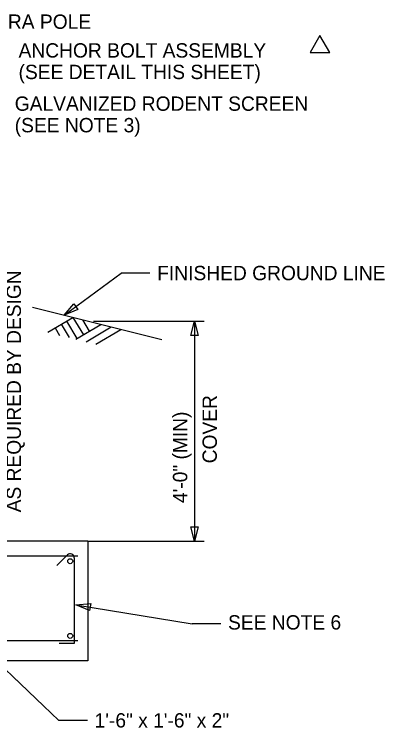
# Model space of a CAD drawing. Extents: x 1299104.6 to 1299141.4, y 239713.3 to 239735.3.
# Drawn here: x 1299113.29 to 1299116.38, y 239717.46 to 239723.43 of the extents above; entities that cross this region are included whole.
import ezdxf

# ---------------------------------------------------------------- set-up
doc = ezdxf.new("R2010")
doc.units = 0
for name, color, linetype in [('DIM TXT', 7, 'Continuous'), ('Level 3', 7, 'Continuous'), ('Level 8', 7, 'Continuous')]:
    doc.layers.add(name, color=color, linetype=linetype)

msp = doc.modelspace()

# ---------------------------------------------------------------- linework, layer by layer
at = {"layer": 'DIM TXT'}
msp.add_lwpolyline([(1299115.759, 239723.1111), (1299115.9214, 239723.1111), (1299115.8402, 239723.2517)], close=True, dxfattribs=at)
at = {"layer": 'Level 3'}
for p, q in [((1299113.4376, 239720.979), (1299114.5182, 239720.7088)), ((1299113.8995, 239719.022), (1299112.3995, 239719.022)), ((1299113.8995, 239719.022), (1299113.8995, 239718.022)), ((1299113.8162, 239718.897), (1299109.4828, 239718.897)), ((1299113.6416, 239718.8196), (1299113.73, 239718.908)), ((1299113.7872, 239718.8843), (1299113.7872, 239718.1678)), ((1299113.8162, 239718.1887), (1299109.4828, 239718.1887)), ((1299113.7872, 239718.1678), (1299113.6622, 239718.1678)), ((1299113.8995, 239718.022), (1299109.3995, 239718.022))]:
    msp.add_line(p, q, dxfattribs=at)
for centre in [(1299113.7537, 239718.8553), (1299113.7537, 239718.2303)]:
    msp.add_circle(centre, 0.0208, dxfattribs=at)
msp.add_arc((1299113.7537, 239718.8843), 0.0335, 0, 135, dxfattribs=at)
at = {"layer": 'Level 8'}
for p, q in [((1299113.7041, 239720.9123), (1299114.1802, 239721.2654)), ((1299114.4202, 239721.2654), (1299114.1802, 239721.2654)), ((1299113.5674, 239720.7706), (1299113.7755, 239720.8945)), ((1299113.723, 239720.8633), (1299113.8096, 239720.7177)), ((1299113.7764, 239720.8943), (1299113.8633, 239720.7482)), ((1299113.8571, 239720.8741), (1299113.9133, 239720.7795)), ((1299113.9485, 239720.8635), (1299114.873, 239720.8635)), ((1299114.7917, 239720.8635), (1299114.7917, 239719.022)), ((1299113.6272, 239720.8062), (1299113.6647, 239720.743)), ((1299113.6779, 239720.8364), (1299113.7436, 239720.7259)), ((1299113.8003, 239720.7115), (1299114.0096, 239720.836)), ((1299113.8858, 239720.6897), (1299114.0955, 239720.8145)), ((1299113.9668, 239720.6692), (1299114.1768, 239720.7942)), ((1299112.0297, 239719.0767), (1299113.6573, 239717.5239)), ((1299113.8995, 239719.022), (1299114.873, 239719.022)), ((1299113.8019, 239718.4913), (1299114.7721, 239718.3301)), ((1299115.0121, 239718.3301), (1299114.7721, 239718.3301)), ((1299113.8973, 239717.5239), (1299113.6573, 239717.5239))]:
    msp.add_line(p, q, dxfattribs=at)
for points in [[(1299113.8184, 239720.9597), (1299113.7041, 239720.9123), (1299113.7826, 239721.0079)], [(1299114.7617, 239720.7435), (1299114.7917, 239720.8635), (1299114.8217, 239720.7435)], [(1299114.8217, 239719.142), (1299114.7917, 239719.022), (1299114.7617, 239719.142)], [(1299113.9153, 239718.4421), (1299113.8019, 239718.4913), (1299113.9251, 239718.5013)]]:
    msp.add_lwpolyline(points, close=True, dxfattribs=at)

# ---------------------------------------------------------------- texts
at = {"layer": 'DIM TXT'}
for s, p in [('  CCTV CAMERA POLE', (1299112.1986, 239723.3081)), ('ANCHOR BOLT ASSEMBLY', (1299113.322, 239723.0676)), ('(SEE DETAIL THIS SHEET)', (1299113.322, 239722.8876)), ('GALVANIZED RODENT SCREEN', (1299113.29, 239722.6224)), ('(SEE NOTE 3)', (1299113.29, 239722.4424)), ('FINISHED GROUND LINE', (1299114.4802, 239721.2054)), ('SEE NOTE 6', (1299115.0721, 239718.2834)), ('1\'-6" x 1\'-6" x 2"', (1299113.9573, 239717.4639))]:
    msp.add_text(s, height=0.12, dxfattribs=at).set_placement(p)
for s, p in [('AS REQUIRED BY DESIGN', (1299113.3418, 239719.2638)), ('COVER', (1299114.9789, 239719.6738)), ('4\'-0" (MIN)', (1299114.7317, 239719.3417))]:
    msp.add_text(s, height=0.12, rotation=90, dxfattribs=at).set_placement(p)

doc.saveas('drawing.dxf')
